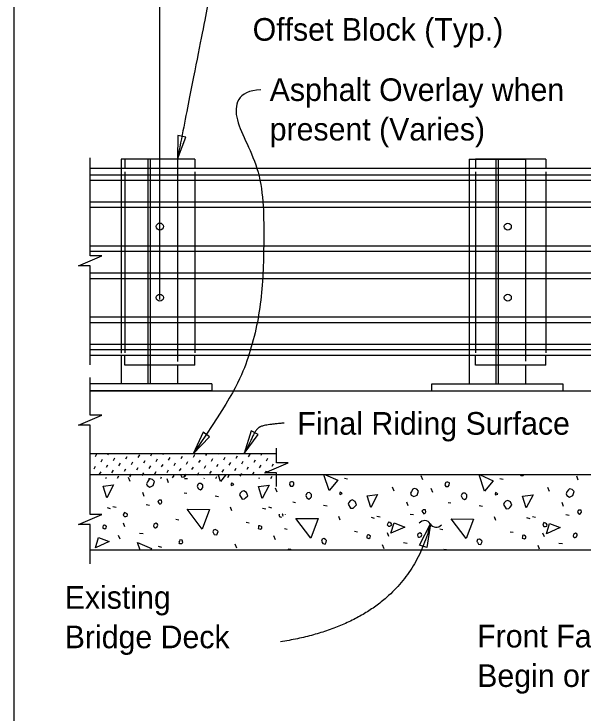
# Model space of a CAD drawing. Extents: x 21526.6 to 21598.7, y 56118.9 to 56155.9.
# Drawn here: x 21545.72 to 21550.79, y 56132.33 to 56138.57 of the extents above; entities that cross this region are included whole.
import ezdxf

# ---------------------------------------------------------------- set-up
doc = ezdxf.new("R2010")
doc.units = 0
for name, color, linetype in [('AdhocPoint_dp', 7, 'Continuous'), ('Border', 7, 'Continuous'), ('Patterning', 7, 'Continuous'), ('PlotBorder_dp', 7, 'Continuous'), ('SheetBorder_dp', 7, 'Continuous'), ('TextMisc', 7, 'Continuous')]:
    doc.layers.add(name, color=color, linetype=linetype)

msp = doc.modelspace()

# ---------------------------------------------------------------- linework, layer by layer
at = {"layer": 'AdhocPoint_dp'}
for p, q in [((21546.3955, 56135.21), (21554.1792, 56135.21)), ((21548.0534, 56134.6483), (21546.3955, 56134.6483)), ((21554.1792, 56134.46), (21546.3955, 56134.46)), ((21546.3955, 56133.7933), (21554.1792, 56133.7933))]:
    msp.add_line(p, q, dxfattribs=at)
at = {"layer": 'Patterning'}
for p, q in [((21547.0151, 56136.0224), (21547.0151, 56142.7213)), ((21547.3276, 56137.2726), (21546.7026, 56137.2726)), ((21546.7026, 56137.2726), (21546.7026, 56137.1892)), ((21547.3276, 56137.2726), (21547.3276, 56137.1892)), ((21550.4525, 56137.2724), (21549.8275, 56137.2724)), ((21549.8275, 56137.2724), (21549.8275, 56137.1891)), ((21550.4525, 56137.2724), (21550.4525, 56137.1891)), ((21546.7026, 56137.1607), (21546.7026, 56135.5488)), ((21547.3276, 56137.1607), (21547.3276, 56135.5488)), ((21549.8275, 56137.1605), (21549.8275, 56135.5487)), ((21550.4525, 56137.1605), (21550.4525, 56135.5487)), ((21546.3955, 56137.1336), (21552.8484, 56137.1336)), ((21546.3955, 56137.0854), (21552.8484, 56137.0854)), ((21546.3955, 56136.8926), (21552.8484, 56136.8926)), ((21546.3955, 56136.8444), (21552.8484, 56136.8444)), ((21546.3955, 56136.5004), (21552.8484, 56136.5004)), ((21546.3955, 56136.4522), (21552.8484, 56136.4522)), ((21546.3955, 56136.2594), (21552.8484, 56136.2594)), ((21546.3955, 56136.2112), (21552.8484, 56136.2112)), ((21546.3955, 56135.8673), (21552.8484, 56135.8673)), ((21546.3955, 56135.8191), (21552.8484, 56135.8191)), ((21546.3955, 56135.6262), (21552.8484, 56135.6262)), ((21546.3955, 56135.578), (21552.8484, 56135.578)), ((21546.7026, 56135.4392), (21546.7026, 56135.5226)), ((21547.3276, 56135.4392), (21547.3276, 56135.5226)), ((21549.8275, 56135.4391), (21549.8275, 56135.5224)), ((21550.4525, 56135.4391), (21550.4525, 56135.5224)), ((21547.3276, 56135.4392), (21546.7026, 56135.4392)), ((21550.4525, 56135.4391), (21549.8275, 56135.4391)), ((21546.4424, 56134.6258), (21546.4553, 56134.6482)), ((21546.4912, 56134.577), (21546.5042, 56134.5994)), ((21546.553, 56134.6388), (21546.5585, 56134.6483)), ((21546.6018, 56134.59), (21546.6148, 56134.6124)), ((21546.7125, 56134.6029), (21546.7254, 56134.6253)), ((21546.8231, 56134.6159), (21546.8361, 56134.6383)), ((21546.8719, 56134.5671), (21546.8849, 56134.5894)), ((21546.9337, 56134.6289), (21546.945, 56134.6483)), ((21546.9826, 56134.58), (21546.9955, 56134.6024)), ((21547.0444, 56134.6418), (21547.0481, 56134.6483)), ((21547.0932, 56134.593), (21547.1062, 56134.6154)), ((21547.2038, 56134.6059), (21547.2168, 56134.6283)), ((21547.3145, 56134.6189), (21547.3274, 56134.6413)), ((21547.3633, 56134.5701), (21547.3763, 56134.5925)), ((21547.4251, 56134.6319), (21547.4346, 56134.6483)), ((21547.4739, 56134.583), (21547.4869, 56134.6054)), ((21547.5357, 56134.6448), (21547.5378, 56134.6483)), ((21547.5846, 56134.596), (21547.5975, 56134.6184)), ((21547.6952, 56134.609), (21547.7082, 56134.6314)), ((21547.8058, 56134.6219), (21547.8188, 56134.6443)), ((21547.8547, 56134.5731), (21547.8676, 56134.5955)), ((21547.9165, 56134.6349), (21547.9242, 56134.6483)), ((21547.9653, 56134.5861), (21547.9783, 56134.6084)), ((21548.0271, 56134.6479), (21548.0274, 56134.6483)), ((21546.4294, 56134.5152), (21546.4424, 56134.5376)), ((21546.54, 56134.5282), (21546.553, 56134.5506)), ((21546.6507, 56134.5411), (21546.6636, 56134.5635)), ((21546.7613, 56134.5541), (21546.7743, 56134.5765)), ((21546.8101, 56134.5053), (21546.8231, 56134.5276)), ((21546.9208, 56134.5182), (21546.9337, 56134.5406)), ((21547.0314, 56134.5312), (21547.0444, 56134.5536)), ((21547.142, 56134.5441), (21547.155, 56134.5665)), ((21547.2527, 56134.5571), (21547.2656, 56134.5795)), ((21547.3015, 56134.5083), (21547.3145, 56134.5307)), ((21547.4121, 56134.5212), (21547.4251, 56134.5436)), ((21547.5228, 56134.5342), (21547.5357, 56134.5566)), ((21547.6334, 56134.5472), (21547.6464, 56134.5696)), ((21547.744, 56134.5601), (21547.757, 56134.5825)), ((21547.7929, 56134.5113), (21547.8058, 56134.5337)), ((21547.9035, 56134.5243), (21547.9165, 56134.5467)), ((21548.0141, 56134.5372), (21548.0271, 56134.5596)), ((21546.4782, 56134.4664), (21546.4912, 56134.4888)), ((21546.5889, 56134.4793), (21546.6018, 56134.5017)), ((21546.6995, 56134.4923), (21546.7125, 56134.5147)), ((21546.7483, 56134.4435), (21546.7613, 56134.4658)), ((21546.859, 56134.4564), (21546.8719, 56134.4788)), ((21546.9696, 56134.4694), (21546.9826, 56134.4918)), ((21547.0802, 56134.4823), (21547.0932, 56134.5047)), ((21547.1909, 56134.4953), (21547.2038, 56134.5177)), ((21547.2397, 56134.4465), (21547.2527, 56134.4689)), ((21547.3503, 56134.4594), (21547.3633, 56134.4818)), ((21547.461, 56134.4724), (21547.4739, 56134.4948)), ((21547.5716, 56134.4854), (21547.5846, 56134.5078)), ((21547.6822, 56134.4983), (21547.6952, 56134.5207)), ((21547.7311, 56134.4495), (21547.744, 56134.4719)), ((21547.8417, 56134.4625), (21547.8547, 56134.4849)), ((21547.9523, 56134.4754), (21547.9653, 56134.4978)), ((21548.063, 56134.4884), (21548.0631, 56134.4886)), ((21546.5339, 56134.4293), (21546.54, 56134.4399)), ((21546.6377, 56134.4305), (21546.6507, 56134.4529)), ((21546.7494, 56134.4017), (21546.7352, 56134.4371)), ((21546.9204, 56134.4293), (21546.9208, 56134.43)), ((21547.0235, 56134.4293), (21547.0314, 56134.4429)), ((21547.0935, 56134.3899), (21547.0793, 56134.4253)), ((21547.1291, 56134.4335), (21547.142, 56134.4559)), ((21547.41, 56134.4293), (21547.4121, 56134.433)), ((21547.5132, 56134.4293), (21547.5228, 56134.446)), ((21547.6204, 56134.4365), (21547.6334, 56134.4589)), ((21547.8996, 56134.4293), (21547.9035, 56134.436)), ((21548.0028, 56134.4293), (21548.0141, 56134.449)), ((21548.659, 56134.4328), (21548.6873, 56134.4258)), ((21549.3573, 56134.4169), (21549.3431, 56134.4523)), ((21550.0437, 56134.4293), (21550.072, 56134.4222)), ((21550.742, 56134.4134), (21550.7278, 56134.4487)), ((21548.0604, 56134.3079), (21548.0462, 56134.3433)), ((21549.101, 56134.3162), (21549.0868, 56134.3515)), ((21549.4451, 56134.3044), (21549.4309, 56134.3398)), ((21550.4856, 56134.3126), (21550.4715, 56134.348)), ((21546.8749, 56134.2691), (21546.8625, 56134.3027)), ((21547.2313, 56134.3016), (21547.2561, 56134.298)), ((21547.5071, 56134.2733), (21547.5372, 56134.268)), ((21548.1983, 56134.2196), (21548.223, 56134.216)), ((21549.2265, 56134.1836), (21549.2141, 56134.2172)), ((21549.5829, 56134.216), (21549.6077, 56134.2125)), ((21550.6112, 56134.18), (21550.5988, 56134.2136)), ((21546.5449, 56134.169), (21546.5732, 56134.1619)), ((21546.5973, 56134.179), (21546.6256, 56134.1719)), ((21546.8937, 56134.1973), (21546.9238, 56134.192)), ((21547.6556, 56134.1389), (21547.6432, 56134.1725)), ((21547.9296, 56134.1654), (21547.9579, 56134.1584)), ((21547.982, 56134.1754), (21548.0103, 56134.1684)), ((21548.474, 56134.1913), (21548.5041, 56134.186)), ((21549.8587, 56134.1877), (21549.8888, 56134.1824)), ((21548.6225, 56134.0569), (21548.6102, 56134.0905)), ((21548.9489, 56134.0934), (21548.9772, 56134.0864)), ((21549.2453, 56134.1117), (21549.2753, 56134.1064)), ((21550.3336, 56134.0899), (21550.3619, 56134.0828)), ((21550.63, 56134.1082), (21550.66, 56134.1029)), ((21546.7034, 56133.9964), (21546.691, 56134.0299)), ((21547.1571, 56134.0647), (21547.1836, 56134.0594)), ((21547.7829, 56134.0399), (21547.8094, 56134.0346)), ((21548.8965, 56134.0834), (21548.9248, 56134.0764)), ((21550.0072, 56134.0534), (21549.9948, 56134.087)), ((21550.2812, 56134.0799), (21550.3095, 56134.0728)), ((21548.124, 56133.9827), (21548.1505, 56133.9774)), ((21549.5087, 56133.9791), (21549.5352, 56133.9738)), ((21546.661, 56133.8868), (21546.6468, 56133.9221)), ((21546.8336, 56133.9427), (21546.8654, 56133.9392)), ((21548.0457, 56133.8832), (21548.0315, 56133.9186)), ((21548.7498, 56133.9579), (21548.7763, 56133.9526)), ((21549.055, 56133.9108), (21549.0426, 56133.9444)), ((21550.1345, 56133.9544), (21550.161, 56133.9491)), ((21550.4397, 56133.9073), (21550.4273, 56133.9409)), ((21547.6998, 56133.8084), (21547.6857, 56133.8437)), ((21549.1852, 56133.8572), (21549.217, 56133.8536)), ((21550.5699, 56133.8536), (21550.6017, 56133.8501)), ((21547.0015, 56133.8243), (21547.0298, 56133.8172)), ((21549.0126, 56133.8012), (21548.9984, 56133.8366)), ((21550.3973, 56133.7977), (21550.3831, 56133.833))]:
    msp.add_line(p, q, dxfattribs=at)
for points in [[(21546.9032, 56134.3646), (21546.9261, 56134.3522), (21546.9562, 56134.3646), (21546.9686, 56134.4017), (21546.9509, 56134.4194), (21546.9279, 56134.4247), (21546.9173, 56134.4176), (21546.9049, 56134.3982), (21546.8961, 56134.3823), (21546.9032, 56134.3646)], [(21547.2033, 56134.4566), (21547.2119, 56134.4412), (21547.2313, 56134.443), (21547.2402, 56134.4554), (21547.2403, 56134.4566)], [(21547.2354, 56134.4293), (21547.2364, 56134.4269), (21547.234, 56134.4293)], [(21547.2364, 56134.4269), (21547.2576, 56134.4269), (21547.2601, 56134.4293)], [(21547.5548, 56134.4023), (21547.5372, 56134.4566)], [(21547.6008, 56134.4566), (21547.5548, 56134.4023)], [(21548.17, 56134.3751), (21548.1788, 56134.3592), (21548.1983, 56134.361), (21548.2071, 56134.3734), (21548.2089, 56134.3928), (21548.1965, 56134.3981), (21548.1877, 56134.3999), (21548.177, 56134.3963), (21548.1735, 56134.3928), (21548.17, 56134.3751)], [(21548.5218, 56134.3203), (21548.4763, 56134.46)], [(21548.4902, 56134.46), (21548.5995, 56134.4122), (21548.5218, 56134.3203)], [(21549.9064, 56134.3168), (21549.8599, 56134.46)], [(21549.8668, 56134.46), (21549.9842, 56134.4087), (21549.9064, 56134.3168)], [(21550.2285, 56134.46), (21550.2311, 56134.454), (21550.2275, 56134.4576)], [(21550.2311, 56134.454), (21550.2523, 56134.454), (21550.2582, 56134.46)], [(21546.5425, 56134.255), (21546.509, 56134.3593), (21546.6026, 56134.3716), (21546.5425, 56134.255)], [(21547.348, 56134.3581), (21547.3586, 56134.3369), (21547.3763, 56134.3263), (21547.3904, 56134.3369), (21547.3975, 56134.3475), (21547.3975, 56134.3687), (21547.3816, 56134.3846), (21547.3622, 56134.3829), (21547.3533, 56134.374), (21547.348, 56134.3581)], [(21547.6538, 56134.367), (21547.6733, 56134.3758), (21547.6662, 56134.3829), (21547.6538, 56134.3882), (21547.6485, 56134.3758), (21547.6538, 56134.367)], [(21547.9272, 56134.2514), (21547.8936, 56134.3557), (21547.9873, 56134.3681), (21547.9272, 56134.2514)], [(21549.2548, 56134.279), (21549.2777, 56134.2667), (21549.3078, 56134.279), (21549.3202, 56134.3162), (21549.3025, 56134.3338), (21549.2795, 56134.3391), (21549.2689, 56134.3321), (21549.2565, 56134.3126), (21549.2477, 56134.2967), (21549.2548, 56134.279)], [(21549.5547, 56134.3716), (21549.5635, 56134.3557), (21549.5829, 56134.3574), (21549.5918, 56134.3698), (21549.5935, 56134.3893), (21549.5812, 56134.3946), (21549.5723, 56134.3963), (21549.5617, 56134.3928), (21549.5582, 56134.3893), (21549.5547, 56134.3716)], [(21547.7245, 56134.2821), (21547.7475, 56134.245), (21547.7705, 56134.2468), (21547.7793, 56134.2556), (21547.7988, 56134.275), (21547.7864, 56134.3051), (21547.7617, 56134.3192), (21547.744, 56134.3122), (21547.7299, 56134.298), (21547.7245, 56134.2821)], [(21548.3149, 56134.2761), (21548.3255, 56134.2549), (21548.3432, 56134.2443), (21548.3574, 56134.2549), (21548.3644, 56134.2655), (21548.3644, 56134.2867), (21548.3485, 56134.3026), (21548.3291, 56134.3009), (21548.3202, 56134.292), (21548.3149, 56134.2761)], [(21548.6208, 56134.285), (21548.6402, 56134.2938), (21548.6331, 56134.3009), (21548.6208, 56134.3062), (21548.6155, 56134.2938), (21548.6208, 56134.285)], [(21548.8941, 56134.1694), (21548.8605, 56134.2737), (21548.9542, 56134.2861), (21548.8941, 56134.1694)], [(21549.6996, 56134.2726), (21549.7102, 56134.2514), (21549.7279, 56134.2408), (21549.742, 56134.2514), (21549.7491, 56134.262), (21549.7491, 56134.2832), (21549.7332, 56134.2991), (21549.7138, 56134.2973), (21549.7049, 56134.2885), (21549.6996, 56134.2726)], [(21550.0054, 56134.2814), (21550.0249, 56134.2903), (21550.0178, 56134.2973), (21550.0054, 56134.3026), (21550.0001, 56134.2903), (21550.0054, 56134.2814)], [(21550.2788, 56134.1659), (21550.2452, 56134.2702), (21550.3389, 56134.2826), (21550.2788, 56134.1659)], [(21550.6394, 56134.2755), (21550.6624, 56134.2631), (21550.6925, 56134.2755), (21550.7048, 56134.3126), (21550.6872, 56134.3303), (21550.6642, 56134.3356), (21550.6536, 56134.3285), (21550.6412, 56134.3091), (21550.6324, 56134.2932), (21550.6394, 56134.2755)], [(21547.0051, 56134.2096), (21547.0157, 56134.199), (21547.0263, 56134.2061), (21547.0334, 56134.2167), (21547.0298, 56134.2344), (21547.021, 56134.2362), (21547.0086, 56134.2344), (21546.998, 56134.2238), (21547.0051, 56134.2096)], [(21548.6915, 56134.2001), (21548.7145, 56134.163), (21548.7374, 56134.1648), (21548.7463, 56134.1736), (21548.7657, 56134.193), (21548.7533, 56134.2231), (21548.7286, 56134.2372), (21548.7109, 56134.2302), (21548.6968, 56134.216), (21548.6915, 56134.2001)], [(21550.0761, 56134.1966), (21550.0991, 56134.1595), (21550.1221, 56134.1612), (21550.1309, 56134.1701), (21550.1504, 56134.1895), (21550.138, 56134.2196), (21550.1133, 56134.2337), (21550.0956, 56134.2266), (21550.0815, 56134.2125), (21550.0761, 56134.1966)], [(21547.3922, 56133.9781), (21547.2579, 56134.1548), (21547.4576, 56134.1531), (21547.3922, 56133.9781)], [(21549.3567, 56134.1241), (21549.3673, 56134.1135), (21549.3779, 56134.1206), (21549.3849, 56134.1312), (21549.3814, 56134.1488), (21549.3726, 56134.1506), (21549.3602, 56134.1488), (21549.3496, 56134.1382), (21549.3567, 56134.1241)], [(21546.6999, 56134.0906), (21546.7122, 56134.0888), (21546.7246, 56134.0941), (21546.7282, 56134.1047), (21546.7229, 56134.1136), (21546.7122, 56134.1206), (21546.6999, 56134.1259), (21546.6928, 56134.1118), (21546.6893, 56134.1012), (21546.6999, 56134.0906)], [(21548.0789, 56134.1111), (21548.0775, 56134.1082), (21548.0739, 56134.0976), (21548.0845, 56134.087)], [(21548.1101, 56134.0931), (21548.1128, 56134.1012), (21548.1075, 56134.11), (21548.1059, 56134.1111)], [(21548.133, 56134.1072), (21548.1342, 56134.1111)], [(21550.7413, 56134.1206), (21550.7519, 56134.11), (21550.7626, 56134.117), (21550.7696, 56134.1276), (21550.7661, 56134.1453), (21550.7573, 56134.1471), (21550.7449, 56134.1453), (21550.7343, 56134.1347), (21550.7413, 56134.1206)], [(21546.9697, 56133.9904), (21546.9768, 56133.9904), (21546.9909, 56133.9975), (21546.9962, 56134.0134), (21546.9945, 56134.0223), (21546.9803, 56134.0293), (21546.9626, 56134.0187), (21546.9591, 56134.0081), (21546.9626, 56133.9975), (21546.9697, 56133.9904)], [(21548.0845, 56134.087), (21548.0969, 56134.0853), (21548.0988, 56134.0861)], [(21548.3591, 56133.8961), (21548.2248, 56134.0728), (21548.4245, 56134.0711), (21548.3591, 56133.8961)], [(21549.0515, 56134.005), (21549.0638, 56134.0033), (21549.0762, 56134.0086), (21549.0798, 56134.0192), (21549.0744, 56134.028), (21549.0638, 56134.0351), (21549.0515, 56134.0404), (21549.0444, 56134.0262), (21549.0409, 56134.0156), (21549.0515, 56134.005)], [(21549.0738, 56133.9403), (21549.1021, 56134.0322), (21549.1958, 56133.9951), (21549.0738, 56133.9403)], [(21549.7438, 56133.8925), (21549.6095, 56134.0693), (21549.8092, 56134.0675), (21549.7438, 56133.8925)], [(21550.4361, 56134.0015), (21550.4485, 56133.9997), (21550.4609, 56134.005), (21550.4644, 56134.0156), (21550.4591, 56134.0245), (21550.4485, 56134.0316), (21550.4361, 56134.0369), (21550.4291, 56134.0227), (21550.4255, 56134.0121), (21550.4361, 56134.0015)], [(21550.4585, 56133.9367), (21550.4868, 56134.0286), (21550.5805, 56133.9915), (21550.4585, 56133.9367)], [(21546.506, 56133.9851), (21546.5255, 56133.9798), (21546.5379, 56133.9887), (21546.5396, 56134.001), (21546.5361, 56134.0046), (21546.522, 56134.0116), (21546.5096, 56134.0099), (21546.5078, 56133.9975), (21546.506, 56133.9851)], [(21547.4912, 56133.9462), (21547.5, 56133.9303), (21547.5213, 56133.9268), (21547.5301, 56133.9427), (21547.5336, 56133.9568), (21547.5248, 56133.9657), (21547.5089, 56133.9745), (21547.493, 56133.9692), (21547.4877, 56133.9533), (21547.4912, 56133.9462)], [(21547.8907, 56133.9816), (21547.9102, 56133.9763), (21547.9225, 56133.9851), (21547.9243, 56133.9975), (21547.9208, 56134.001), (21547.9066, 56134.0081), (21547.8943, 56134.0063), (21547.8925, 56133.994), (21547.8907, 56133.9816)], [(21546.4412, 56133.8116), (21546.4695, 56133.9035), (21546.5632, 56133.8664), (21546.4412, 56133.8116)], [(21548.8576, 56133.8996), (21548.8771, 56133.8943), (21548.8895, 56133.9031), (21548.8912, 56133.9155), (21548.8877, 56133.919), (21548.8735, 56133.9261), (21548.8612, 56133.9243), (21548.8594, 56133.912), (21548.8576, 56133.8996)], [(21549.3213, 56133.9049), (21549.3284, 56133.9049), (21549.3425, 56133.912), (21549.3478, 56133.9279), (21549.3461, 56133.9367), (21549.3319, 56133.9438), (21549.3142, 56133.9332), (21549.3107, 56133.9226), (21549.3142, 56133.912), (21549.3213, 56133.9049)], [(21550.2423, 56133.8961), (21550.2618, 56133.8908), (21550.2741, 56133.8996), (21550.2759, 56133.912), (21550.2724, 56133.9155), (21550.2582, 56133.9226), (21550.2459, 56133.9208), (21550.2441, 56133.9084), (21550.2423, 56133.8961)], [(21550.706, 56133.9014), (21550.7131, 56133.9014), (21550.7272, 56133.9084), (21550.7325, 56133.9243), (21550.7307, 56133.9332), (21550.7166, 56133.9403), (21550.6989, 56133.9296), (21550.6954, 56133.919), (21550.6989, 56133.9084), (21550.706, 56133.9014)], [(21546.8388, 56133.79), (21546.8165, 56133.8585), (21546.9421, 56133.8037), (21546.9305, 56133.79)], [(21547.1889, 56133.849), (21547.2101, 56133.849), (21547.2207, 56133.8596), (21547.2154, 56133.8791), (21547.1925, 56133.8808), (21547.1889, 56133.8702), (21547.1836, 56133.8614), (21547.1889, 56133.849), (21547.1854, 56133.8525)], [(21548.4581, 56133.8642), (21548.467, 56133.8483), (21548.4882, 56133.8448), (21548.497, 56133.8607), (21548.5006, 56133.8748), (21548.4917, 56133.8837), (21548.4758, 56133.8925), (21548.4599, 56133.8872), (21548.4546, 56133.8713), (21548.4581, 56133.8642)], [(21549.8428, 56133.8607), (21549.8516, 56133.8448), (21549.8729, 56133.8413), (21549.8817, 56133.8572), (21549.8852, 56133.8713), (21549.8764, 56133.8801), (21549.8605, 56133.889), (21549.8446, 56133.8837), (21549.8393, 56133.8678), (21549.8428, 56133.8607)], [(21546.5368, 56133.79), (21546.5302, 56133.7913), (21546.5262, 56133.79)], [(21548.1834, 56133.7933), (21548.1824, 56133.7971), (21548.1594, 56133.7988), (21548.1575, 56133.7933)], [(21549.5671, 56133.7933), (21549.567, 56133.7935), (21549.544, 56133.7953), (21549.5434, 56133.7933)]]:
    msp.add_lwpolyline(points, dxfattribs=at)
at = {"layer": 'PlotBorder_dp'}
msp.add_line((21545.7163, 56153.2556), (21545.7163, 56127.3172), dxfattribs=at)
for points in [[(21547.1713, 56137.2726), (21547.2461, 56137.4701), (21547.1768, 56137.4837)], [(21547.3105, 56134.6482), (21547.4577, 56134.7997), (21547.3996, 56134.8397)], [(21547.7672, 56134.6496), (21547.8919, 56134.8201), (21547.8288, 56134.8517)], [(21549.4247, 56134.0233), (21549.3942, 56133.8143), (21549.3271, 56133.836)]]:
    msp.add_lwpolyline(points, close=True, dxfattribs=at)
for points in [[(21546.3955, 56135.4395), (21546.3955, 56136.3228), (21546.2921, 56136.3228), (21546.3955, 56136.3678), (21546.4988, 56136.4128), (21546.3955, 56136.4128), (21546.3955, 56137.2857)], [(21546.3955, 56134.4321), (21546.3955, 56134.9022), (21546.2921, 56134.9022), (21546.3955, 56134.9472), (21546.4988, 56134.9922), (21546.3955, 56134.9922), (21546.3955, 56135.3267)], [(21548.0534, 56134.3575), (21548.0534, 56134.4784), (21547.9501, 56134.4784), (21548.0534, 56134.5234), (21548.1568, 56134.5684), (21548.0534, 56134.5684), (21548.0534, 56134.699)], [(21546.3955, 56133.667), (21546.3955, 56134.0177), (21546.2921, 56134.0177), (21546.3955, 56134.0627), (21546.4988, 56134.1077), (21546.3955, 56134.1077), (21546.3955, 56134.4321)]]:
    msp.add_lwpolyline(points, dxfattribs=at)
for centre, start, end in [((21549.3723, 56133.9936), 30.00813, 141.73535), ((21549.4755, 56134.0532), 210.00813, 321.73535)]:
    msp.add_arc(centre, 0.0596, start, end, dxfattribs=at)
for points, degree in [([(21547.7365, 56139.0917), (21547.573, 56139.0917), (21547.5207, 56139.0394), (21547.4226, 56138.552), (21547.1713, 56137.2726)], 2), ([(21547.9147, 56137.8914), (21547.7027, 56137.8805), (21547.6407, 56137.6336), (21547.9384, 56137.195), (21547.9442, 56136.5212), (21547.927, 56135.9787), (21547.8072, 56135.4705), (21547.6617, 56135.1578), (21547.3105, 56134.6481)], 3), ([(21548.1235, 56134.922), (21547.9499, 56134.9066), (21547.8757, 56134.8752), (21547.8101, 56134.7353), (21547.7672, 56134.6496)], 2), ([(21549.4247, 56134.0233), (21549.2041, 56133.1495), (21548.0898, 56132.9735)], 2)]:
    msp.add_open_spline(points, degree=degree, dxfattribs=at)
at = {"layer": 'SheetBorder_dp'}
for p, q in [((21546.6713, 56137.2726), (21546.6713, 56135.5456)), ((21546.9109, 56135.2726), (21546.9109, 56137.2726)), ((21546.9317, 56135.2726), (21546.9317, 56137.2726)), ((21547.1713, 56137.2726), (21547.1713, 56135.4691)), ((21550.0101, 56135.2724), (21550.0101, 56137.2724)), ((21550.0309, 56135.2724), (21550.0309, 56137.2724)), ((21550.2705, 56137.2724), (21550.2705, 56135.4745)), ((21549.7705, 56137.1891), (21549.7705, 56135.5224))]:
    msp.add_line(p, q, dxfattribs=at)
at = {"layer": 'TextMisc'}
for p, q in [((21547.1713, 56137.2726), (21546.6713, 56137.2726)), ((21549.7705, 56137.2724), (21550.2705, 56137.2724)), ((21549.7705, 56137.2724), (21549.7705, 56137.1891)), ((21552.8484, 56137.1892), (21546.3955, 56137.1892)), ((21552.8484, 56135.5225), (21546.3955, 56135.5225)), ((21546.6713, 56135.5225), (21546.6713, 56135.2726)), ((21549.7705, 56135.5224), (21549.7705, 56135.2724)), ((21547.1713, 56135.4392), (21547.1713, 56135.2726)), ((21550.2705, 56135.4391), (21550.2705, 56135.2724)), ((21547.4788, 56135.2726), (21546.3955, 56135.2726)), ((21547.1713, 56135.2726), (21546.6713, 56135.2726)), ((21547.4788, 56135.2726), (21547.4788, 56135.2101)), ((21549.4371, 56135.2724), (21550.6038, 56135.2724)), ((21549.4371, 56135.2099), (21549.4371, 56135.2724)), ((21549.7705, 56135.2724), (21550.2705, 56135.2724)), ((21550.6038, 56135.2724), (21550.6038, 56135.2099)), ((21547.4788, 56135.2101), (21546.3955, 56135.2101)), ((21549.4371, 56135.2099), (21550.6038, 56135.2099))]:
    msp.add_line(p, q, dxfattribs=at)
for centre in [(21547.0151, 56136.6725), (21550.1142, 56136.6723), (21547.0151, 56136.0393), (21550.1142, 56136.0392)]:
    msp.add_circle(centre, 0.0312, dxfattribs=at)

# ---------------------------------------------------------------- texts
at = {"layer": 'Border'}
msp.add_text('Final Riding Surface', height=0.2016, dxfattribs=at).set_placement((21548.2396, 56134.8183))
at = {"layer": 'PlotBorder_dp'}
for s, p in [('Offset Block (Typ.)', (21547.8417, 56138.3277)), ('Asphalt Overlay when', (21547.9936, 56137.791)), ('present (Varies)', (21547.9936, 56137.439)), ('Existing ', (21546.168, 56133.2685)), ('Bridge Deck', (21546.168, 56132.9165)), ('Front Face of Backwall &', (21549.8416, 56132.9237)), ('Begin or End Bridge', (21549.8416, 56132.5717))]:
    msp.add_text(s, height=0.2016, dxfattribs=at).set_placement(p)

doc.saveas('drawing.dxf')
